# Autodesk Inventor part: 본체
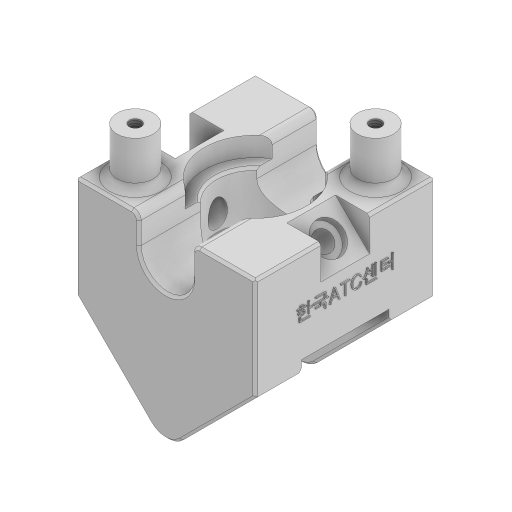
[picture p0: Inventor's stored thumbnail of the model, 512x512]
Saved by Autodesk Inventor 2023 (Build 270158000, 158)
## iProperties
Created: 2025-02
Part Number: 본체
Material: 일반
Document SubType Name: Modeling
Designer: home
Density: 1 g/cm^3
Appearance: 기본값
Author: home
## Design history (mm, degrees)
sketch "스케치1"
  geometry: L1 (-37, 21)-(37, 21); L2 (37, 21)-(37, -21); L3 (-37, -21)-(-37, 21); L4 (-37, 21)-(37, -21); L5 (37, 21)-(-37, -21); L6 (-37, -21)-(0, -58); L7 (0, -58)-(37, -21); 1 further point
  constraints: 14 end point, 2 midpoint, 1 horizontal, 1 parallel, 1 perpendicular, 1 vertical alignment
  dimensions: "d0" = 74 distance of L1.start L1.end; "d2" = 90 deg angle of L7 L6; "d3" = 42 distance of L1.end L2.end
extrude "돌출1" new body sketch "스케치1" stored distance "d4" = 74; taper "d5" = 0 deg
sketch "스케치2"
  geometry: C1 r 21 at (37, 37); C2 r 16 at (37, 37); 1 further point
  constraints: 2 centre point, 2 coincident
  dimensions: "d6" = 42 diameter of C1; "d8" = 32 diameter of C2
extrude "돌출2" cut sketch "스케치2" distance "d9" = 28; taper "d10" = 0 deg
sketch "스케치3"
  geometry: C1 r 16 at (37, 37) reference; C2 r 21 at (37, 37)
  constraints: 1 centre point, 1 coincident
  dimensions: "d11" = 42 diameter of C2
extrude "돌출3" cut sketch "스케치3" distance "d12" = 8; taper "d13" = 0 deg
sketch "스케치4"
  geometry: C1 r 21 at (37, 37) reference; A1 r 7.5 centre (61.749, 61.749) between (66.453, 55.908) and (55.908, 66.453); A2 r 7.5 centre (12.251, 12.251) between (7.547, 18.092) and (18.092, 7.547); A3 r 35 centre (37, 37) between (55.908, 66.453) and (7.547, 18.092); A4 r 35 centre (37, 37) between (18.092, 7.547) and (66.453, 55.908)
  constraints: 8 point on circle, 4 centre point, 1 coincident
  dimensions: "d15" = 15 diameter of A1; "d16" = 15 diameter of A2
extrude "돌출4" join sketch "스케치4" distance "d17" = 19; taper "d18" = 0 deg
sketch "스케치5"
  geometry: L1 (0, -58)-(-37, -21) reference; L2 (-37, -21)-(-37, 21) reference; L3 (-37, 21)-(-21, 21) reference; L4 (-21, 21)-(-21, 13) reference; L5 (-21, 13)-(-16, 13) reference; L6 (-16, 13)-(-16, -7) reference; L7 (-16, -7)-(16, -7) reference; L8 (16, -7)-(16, 13) reference; L9 (16, 13)-(21, 13) reference; L10 (21, 13)-(21, 21) reference; L11 (21, 21)-(37, 21) reference; L12 (37, 21)-(37, -21) reference; L13 (37, -21)-(0, -58) reference; L14 (11, 9)-(11, 41.342); L15 (11, 41.342)-(-11, 41.342); L16 (-11, 41.342)-(-11, 9); L17 (0, 9)-(-11, 9); L18 (0, 9)-(11, 9); A1 r 11 centre (0, 9) between (11, 9) and (-11, 9); 1 further point
  constraints: 10 end point, 2 point on circle, 1 centre point, 1 collinear, 1 perpendicular, 1 tangent, 1 vertical, 1 vertical alignment
  dimensions: "d19" = 22 diameter of A1; "d20" = 12 distance from line of L17.start L3; "d21" = 22 distance of L14.end L15.end
extrude "돌출5" cut sketch "스케치5" extent not by distance; stored distance "d22" = 0; taper "d23" = 0 deg
sketch "스케치6"
  geometry: L1 (0, -58)-(-37, -21) reference; L2 (-37, -21)-(-37, 21) reference; L3 (-37, 21)-(-21, 21) reference; L4 (-21, 21)-(-21, 13) reference; L5 (-21, 13)-(-16, 13) reference; L6 (-16, 13)-(-16, -7) reference; L7 (-16, -7)-(16, -7) reference; L8 (16, -7)-(16, 13) reference; L9 (16, 13)-(21, 13) reference; L10 (21, 13)-(21, 21) reference; L11 (21, 21)-(37, 21) reference; L12 (37, 21)-(37, -21) reference; L13 (37, -21)-(0, -58) reference; L14 (11, 21)-(37, 21) reference; L15 (23, 21)-(37, 7); L16 (37, 21)-(37, -21) reference; L17 (-23, 21)-(-37, 7); 3 further points
  constraints: 4 end point, 4 point on line
  dimensions: "d24" = 14 distance of L11.end L15.start; "d25" = 14 distance of L15.end L11.end; "d26" = 14 distance of L17.start L2.end; "d27" = 14 distance of L17.end L2.end
extrude "돌출6" cut sketch "스케치6" stored distance "d28" = 20; taper "d29" = 0 deg
sketch "스케치8"
  geometry: L1 (0, 0)-(19.799, 0) reference; L2 (9.899, 20)-(19.799, 20) reference; L3 (9.899, 20)-(9.899, 0); 2 further points
  constraints: 2 end point, 2 midpoint
hole "구멍1" sketch "스케치8" at (9.899, 10) diameter "d33" = 8; stored, may be unused: countersink angle "d37" = 90 deg, drill point angle "d39" = 0 deg; dims "d34" = 6, "d35" = 13, "d36" = 3, "d38" = 21
sketch "스케치9"
  geometry: C1 r 7.5 at (0, 0) reference; 1 further point
hole "구멍2" sketch "스케치9" at (0, 0) diameter "d40" = 4.917; stored, may be unused: countersink angle "d44" = 90 deg, drill point angle "d46" = 118 deg; dims "d41" = 12, "d42" = 4, "d43" = 2, "d45" = 14
sketch "스케치10"
  geometry: C1 r 7.5 at (0, 0) reference; 1 further point
hole "구멍3" sketch "스케치10" at (0, 0) diameter "d47" = 4.917; stored, may be unused: countersink angle "d51" = 90 deg, drill point angle "d53" = 118 deg; dims "d48" = 12, "d49" = 4, "d50" = 2, "d52" = 14
sketch "스케치11"
  geometry: L1 (0, 74)-(0, 0) reference; L2 (11.314, 37)-(0, 37); L3 (-7.657, 19)-(67.343, 19); L4 (67.343, 19)-(67.343, 55); L5 (67.343, 55)-(-7.657, 55); L6 (-7.657, 55)-(-7.657, 19)
  constraints: 10 end point, 2 parallel, 1 horizontal, 1 midpoint, 1 perpendicular, 1 other
  dimensions: "d54" = 36 distance of L5.end L3.start; "d55" = 75 distance of L4.end L5.end
extrude "돌출8" cut sketch "스케치11" distance "d56" = 3; taper "d57" = 0 deg
fillet "모깎기1" dims "d58" = 9
fillet "모깎기2" dims "d59" = 6
fillet "모깎기3" dims "d60" = 3
chamfer "모따기1" distance "d61" = 1; stored, may be unused: second distance "d62" = 2, angle "d63" = 45 deg
fillet "모깎기4" dims "d64" = 3
chamfer "모따기2" distance "d65" = 1; stored, may be unused: second distance "d66" = 2, angle "d67" = 45 deg
chamfer "모따기3" distance "d68" = 1; stored, may be unused: second distance "d69" = 2, angle "d70" = 45 deg
chamfer "모따기4" distance "d71" = 1; stored, may be unused: second distance "d72" = 2, angle "d73" = 45 deg
chamfer "모따기5" distance "d74" = 1; stored, may be unused: second distance "d75" = 2, angle "d76" = 45 deg
chamfer "모따기6" distance "d77" = 1; stored, may be unused: second distance "d78" = 2, angle "d79" = 45 deg
chamfer "모따기7" distance "d80" = 1; stored, may be unused: second distance "d81" = 2, angle "d82" = 45 deg
chamfer "모따기8" distance "d83" = 1; stored, may be unused: second distance "d84" = 2, angle "d85" = 45 deg
chamfer "모따기9" distance "d86" = 1; stored, may be unused: second distance "d87" = 2, angle "d88" = 45 deg
sketch "스케치12"
  geometry: L1 (42.249, 33)-(27.249, 33) reference; L2 (47, -27.586)-(47, 13) reference; 2 further points
  constraints: 1 other
  dimensions: "d89" = 40 distance from line of L1 point (10, -7); "d90" = 37 distance from line of point (10, -7) L2
feature "엠보싱1" sketch "스케치12" dims "d0" = 74, "d2" = 90 deg, "d3" = 42, "d91" = 0.5, "d92" = 0
node "솔리드1"
mirror "미러2"
mirror "미러3"
node "절단 모서리 투영1"
node "절단 모서리 투영2"
feature "A9D066F2-1C7D-4E18-AEED-F7BC21143FA4" dims "d33" = 8, "d34" = 6, "d35" = 13, "d36" = 3, "d37" = 90 deg, "d38" = 21, "d39" = 0
